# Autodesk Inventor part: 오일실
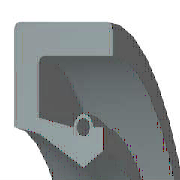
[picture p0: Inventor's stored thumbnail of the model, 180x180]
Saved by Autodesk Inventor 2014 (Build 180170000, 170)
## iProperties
IsCustomPart: 1
Created: 2015-12
Part Number: 오일실
Material: 고무
Description: 오일-실
Document SubType Name: Modeling
Standard: KS B 2804
Designer: mdu
Standards Organization: KS
Language: ko-KR
Size Designation: S - 15 30 7
Categories: <MemberInstance><Categories><Category DisplayName="샤프트 부품" InternalName="7f7aeb1f-a693-4053-b835-cee3144e0d98" Mnemonic="SHFT"><Category DisplayName="실링" Intern
Density: 1 g/cm^3
Mass: 1.76736 g
Surface Area: 26.6454 cm^2
Volume: 1.76736 cm^3
Appearance: 고무 - 검은색 - 버전 1.1
Author: mdu
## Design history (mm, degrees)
revolve "본체" stored, may be unused: angle "d17" = 90 deg
revolve "스프링1" stored, may be unused: angle "d18" = 90 deg
body "Solid1"
sketch "스케치1"
  geometry: L1 (0, 15)-(7, 15); L2 (7, 15)-(7, 13.75); L3 (7, 13.75)-(1.75, 13.75); L4 (0, 15)-(0, 9.6); L5 (0, 9.6)-(1.75, 9.25); L6 (1.75, 9.25)-(4.9, 7.5); L7 (4.9, 7.5)-(0, 7.5); L8 (6.3, 8.375)-(6.3, 9.6); L9 (0, 0)-(9.586, 0) reference; L10 (4.9, 7.5)-(6.3, 8.375); L11 (0, 18)-(0, -3) reference; L12 (-1.917, 0)-(11.503, 0) reference; L13 (4.2, 9.6)-(1.75, 10.09); L14 (1.75, 10.09)-(1.75, 13.75); L15 (6.3, 9.6)-(5.6, 9.6); C1 r 0.455 at (4.9, 9.6); A1 r 0.7 centre (4.9, 9.6) between (5.6, 9.6) and (4.2, 9.6)
  constraints: 26 end point, 5 horizontal alignment, 4 perpendicular, 2 centre point, 2 collinear, 2 horizontal, 2 parallel, 2 point on circle, 2 point on line, 2 vertical alignment, 1 coincident
  dimensions: "d0" = 30 diameter of L1 L9 (= SD2); "d1" = 16.75 diameter of L8.start L9 (= ABDM); "d2" = 1.25 distance of L1.end L2.end (computed from SD); "d3" = 0.91 diameter of C1 (= SPDI); "d4" = 1.4 diameter of A1 (= SPDA); "d5" = 15 diameter of L6.end L9 (= NND); "d6" = 18.5 diameter of L5.end L9 (= TKDM); "d7" = 19.2 diameter of L4.end L9 (= HLDM); "d8" = 4.9 distance from line of C1.centre L4 (= SPDST); "d9" = 6.3 distance between parallel lines of L8 L4 (= SDI); "d10" = 7 distance between parallel lines of L2 L4 (= SWDT); "d12" = 1.75 distance between parallel lines of L14 L4 (= SD)
fillet "모깎기1" dims "d11" = 0.3 (= RR)
other parameters: "SD2" = 30 [user parameter; used in 1 equation term], "SWDT" = 7 [user parameter; used in 1 equation term], "RR" = 0.3 [user parameter; used in 1 equation term], "SD" = 1.75 [user parameter; used in 2 equation terms], "NND" = 15 [user parameter; used in 1 equation term], "SPDA" = 1.4 [user parameter; used in 1 equation term], "SPDI" = 0.91 [user parameter; used in 1 equation term], "TKDM" = 18.5 [user parameter; used in 1 equation term], "HLDM" = 19.2 [user parameter; used in 1 equation term], "ABDM" = 16.75 [user parameter; used in 1 equation term], "SDI" = 6.3 [user parameter; used in 1 equation term], "SPDST" = 4.9 [user parameter; used in 1 equation term], "d13" = 0, "d14" = 0, "d15" = 0, "LAB" = 0.35 [user parameter]
